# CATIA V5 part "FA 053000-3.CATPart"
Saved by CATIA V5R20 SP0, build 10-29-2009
Part number: FA 053000-3
Revision: ANY
Definition: UNKNOWN
Nomenclature: FA 053000-3
Source: Unknown
Bounding box of the stored display mesh (mm): x 0 to 2, y -1.45 to 1.45, z -1.45 to 1.45
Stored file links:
  C:\Users\Utente\Desktop\IO LAVORO\3D X SITO CF\CUMSA\3D files FA\FA 0530SF\FA 053000-3.CATPart

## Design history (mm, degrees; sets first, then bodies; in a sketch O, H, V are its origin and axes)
Body1 "Revolución1" (main body)
  Solid1: solid without history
